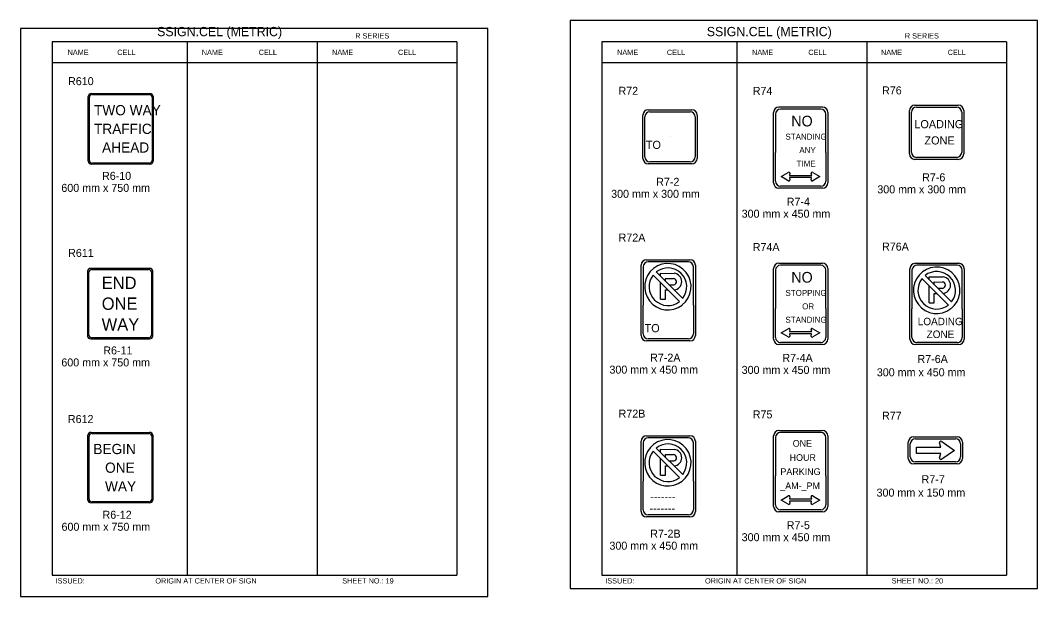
# Model space of a CAD drawing. Extents: x -12 to 6962, y -3756 to 679.
# Drawn here: x -11.9 to 369.4, y -468.8 to -252.7 of the extents above; entities that cross this region are included whole.
import ezdxf

# ---------------------------------------------------------------- set-up
doc = ezdxf.new("R2010")
doc.units = 0
for name, color, linetype in [('Level 1', 7, 'Continuous'), ('Level 2', 7, 'Continuous'), ('Level 3', 7, 'Continuous'), ('Level 63', 7, 'Continuous')]:
    doc.layers.add(name, color=color, linetype=linetype)

msp = doc.modelspace()

# ---------------------------------------------------------------- linework, layer by layer
at = {"layer": 'Level 1'}
for p, q in [((151.75, -260.71), (0, -260.71)), ((0, -260.71), (0, -460.71)), ((50.58, -260.71), (50.58, -460.71)), ((99.37, -260.71), (99.37, -460.71)), ((151.75, -260.71), (151.75, -460.71)), ((357.75, -260.71), (205.99, -260.71)), ((205.99, -260.71), (205.99, -460.71)), ((256.58, -260.71), (256.58, -460.71)), ((305.36, -260.71), (305.36, -460.71)), ((357.75, -260.71), (357.75, -460.71)), ((151.75, -268.62), (0, -268.62)), ((357.75, -268.62), (205.99, -268.62)), ((14, -305.19), (14, -281.51)), ((15.13, -280.53), (36.35, -280.53)), ((37.48, -281.51), (37.48, -305.19)), ((288.09, -285.91), (273.04, -285.91)), ((323.98, -285.23), (339.03, -285.23)), ((222.19, -303.84), (222.19, -288.79)), ((224.07, -286.91), (239.12, -286.91)), ((241, -288.79), (241, -303.84)), ((271.16, -287.79), (271.16, -302.18)), ((289.97, -302.18), (289.97, -287.79)), ((322.1, -302.16), (322.1, -287.11)), ((340.91, -287.11), (340.91, -302.16)), ((25.74, -293.35), (25.74, -293.35)), ((231.6, -296.32), (231.6, -296.32)), ((331.5, -294.64), (331.5, -294.64)), ((280.57, -300.39), (280.57, -300.39)), ((271.16, -313), (271.16, -302.18)), ((289.97, -302.18), (289.97, -313)), ((339.03, -304.04), (323.98, -304.04)), ((36.35, -306.16), (15.13, -306.16)), ((239.12, -305.72), (224.07, -305.72)), ((273.25, -311.24), (275.89, -309.71)), ((275.92, -312.79), (273.25, -311.24)), ((276.54, -309.98), (276.34, -310.83)), ((276.34, -310.83), (280.51, -310.83)), ((280.51, -311.65), (276.35, -311.65)), ((276.35, -311.65), (276.56, -312.51)), ((280.51, -310.83), (284.69, -310.83)), ((284.68, -311.65), (280.51, -311.65)), ((284.47, -312.51), (284.68, -311.65)), ((284.69, -310.83), (284.48, -309.98)), ((287.78, -311.24), (285.11, -312.79)), ((285.13, -309.71), (287.78, -311.24)), ((288.09, -314.88), (273.04, -314.88)), ((14.93, -346.08), (36.15, -346.08)), ((221.55, -345.05), (221.55, -359.44)), ((238.48, -343.17), (223.43, -343.17)), ((240.36, -359.44), (240.36, -345.05)), ((271.16, -346.36), (271.16, -360.75)), ((288.09, -344.48), (273.04, -344.48)), ((289.97, -360.75), (289.97, -346.36)), ((322.28, -346.38), (322.28, -360.78)), ((339.21, -344.51), (324.16, -344.51)), ((341.09, -360.78), (341.09, -346.38)), ((13.8, -370.74), (13.8, -347.06)), ((37.28, -347.06), (37.28, -370.74)), ((225.27, -348.18), (235.18, -358.09)), ((226.44, -347.02), (236.34, -356.92)), ((326, -349.52), (335.91, -359.43)), ((327.18, -348.36), (337.08, -358.26)), ((229.91, -353.72), (230.79, -353.72)), ((231.24, -351.81), (233.02, -351.81)), ((331.97, -353.15), (333.75, -353.15)), ((230.95, -357.65), (230.95, -357.65)), ((330.65, -355.06), (331.53, -355.06)), ((25.54, -358.9), (25.54, -358.9)), ((221.55, -370.26), (221.55, -359.44)), ((240.36, -359.44), (240.36, -370.26)), ((271.16, -371.57), (271.16, -360.75)), ((280.57, -358.96), (280.57, -358.96)), ((289.97, -360.75), (289.97, -371.57)), ((322.28, -371.6), (322.28, -360.78)), ((331.69, -358.99), (331.69, -358.99)), ((341.09, -360.78), (341.09, -371.6)), ((273.25, -369.81), (275.89, -368.28)), ((275.92, -371.36), (273.25, -369.81)), ((276.54, -368.54), (276.34, -369.4)), ((276.34, -369.4), (280.51, -369.4)), ((280.51, -369.4), (284.69, -369.4)), ((284.69, -369.4), (284.48, -368.54)), ((287.78, -369.81), (285.11, -371.36)), ((285.13, -368.28), (287.78, -369.81)), ((36.15, -371.71), (14.93, -371.71)), ((238.48, -372.14), (223.43, -372.14)), ((288.09, -373.45), (273.04, -373.45)), ((280.51, -370.22), (276.35, -370.22)), ((276.35, -370.22), (276.56, -371.08)), ((284.68, -370.22), (280.51, -370.22)), ((284.47, -371.08), (284.68, -370.22)), ((339.21, -373.48), (324.16, -373.48)), ((15, -407.59), (36.22, -407.59)), ((288.09, -407.21), (273.04, -407.21)), ((13.87, -432.24), (13.87, -408.56)), ((37.35, -408.56), (37.35, -432.24)), ((221.55, -411.06), (221.55, -425.45)), ((238.48, -409.18), (223.43, -409.18)), ((240.36, -425.45), (240.36, -411.06)), ((271.16, -409.09), (271.16, -423.48)), ((289.97, -423.48), (289.97, -409.09)), ((321.66, -416.35), (321.66, -411.46)), ((323.54, -409.58), (338.59, -409.58)), ((333.11, -412.71), (332.63, -411.14)), ((333.41, -410.55), (338.26, -413.91)), ((340.47, -411.46), (340.47, -416.35)), ((225.27, -414.19), (235.18, -424.1)), ((226.44, -413.03), (236.34, -422.93)), ((323.94, -415.1), (323.94, -412.71)), ((323.94, -412.71), (333.11, -412.71)), ((333.11, -415.1), (323.94, -415.1)), ((331.06, -413.91), (331.06, -413.91)), ((332.63, -416.67), (333.11, -415.1)), ((338.26, -413.91), (333.41, -417.25)), ((231.24, -417.83), (233.02, -417.83)), ((338.59, -418.23), (323.54, -418.23)), ((25.61, -420.4), (25.61, -420.4)), ((229.91, -419.73), (230.79, -419.73)), ((280.57, -421.7), (280.57, -421.7)), ((221.55, -436.27), (221.55, -425.45)), ((230.95, -423.66), (230.95, -423.66)), ((240.36, -425.45), (240.36, -436.27)), ((271.16, -434.3), (271.16, -423.48)), ((289.97, -423.48), (289.97, -434.3)), ((36.22, -433.22), (15, -433.22)), ((273.25, -432.55), (275.89, -431.01)), ((275.92, -434.09), (273.25, -432.55)), ((276.54, -431.28), (276.34, -432.13)), ((276.34, -432.13), (280.51, -432.13)), ((280.51, -432.95), (276.35, -432.95)), ((276.35, -432.95), (276.56, -433.82)), ((280.51, -432.13), (284.69, -432.13)), ((284.68, -432.95), (280.51, -432.95)), ((284.47, -433.82), (284.68, -432.95)), ((284.69, -432.13), (284.48, -431.28)), ((287.78, -432.55), (285.11, -434.09)), ((285.13, -431.01), (287.78, -432.55)), ((238.48, -438.15), (223.43, -438.15)), ((288.09, -436.18), (273.04, -436.18)), ((0, -460.71), (151.75, -460.71)), ((205.99, -460.71), (357.75, -460.71))]:
    msp.add_line(p, q, dxfattribs=at)
for points in [[(228.01, -348.59), (228.01, -347.51), (233.18, -347.53)], [(229.91, -350.49), (229.91, -349.43), (232.96, -349.44)], [(328.74, -349.93), (328.74, -348.85), (333.92, -348.87)], [(228, -357.23), (228.01, -350.94)], [(228, -357.23), (228, -357.24), (229.91, -357.23), (229.91, -353.72)], [(328.73, -358.57), (328.74, -352.28)], [(330.65, -351.83), (330.65, -350.76), (333.7, -350.78)], [(328.73, -358.57), (328.73, -358.58), (330.65, -358.57), (330.65, -355.06)], [(228.01, -414.6), (228.01, -413.52), (233.18, -413.55)], [(229.91, -416.5), (229.91, -415.44), (232.96, -415.45)], [(228, -423.24), (228.01, -416.95)], [(228, -423.24), (228, -423.25), (229.91, -423.24), (229.91, -419.73)]]:
    msp.add_lwpolyline(points, dxfattribs=at)
for centre, radius, start, end in [((273.04, -287.79), 1.88, 90, 180), ((288.09, -287.79), 1.88, 0, 90), ((323.98, -287.11), 1.88, 90, 180), ((339.03, -287.11), 1.88, 0, 90), ((224.07, -288.79), 1.88, 90, 180), ((239.12, -288.79), 1.88, 0, 90), ((224.07, -303.84), 1.88, 180, 270), ((239.12, -303.84), 1.88, 270, 0), ((323.98, -302.16), 1.88, 180, 270), ((339.03, -302.16), 1.88, 270, 0), ((273.04, -313), 1.88, 180, 270), ((288.09, -313), 1.88, 270, 0), ((223.43, -345.05), 1.88, 90, 180), ((230.8, -352.55), 8.71, 308.1142, 307.7621), ((230.81, -352.55), 7.05, 321.9583, 128.3432), ((238.48, -345.05), 1.88, 0, 90), ((273.04, -346.36), 1.88, 90, 180), ((288.09, -346.36), 1.88, 0, 90), ((324.16, -346.38), 1.88, 90, 180), ((331.54, -353.89), 8.71, 308.1142, 307.7621), ((331.55, -353.89), 7.05, 321.9583, 128.3432), ((339.21, -346.38), 1.88, 0, 90), ((230.81, -352.55), 7.05, 142.1255, 308.3331), ((232.85, -350.63), 1.2, 278.0439, 85.8611), ((232.87, -350.62), 3.11, 274.9803, 84.2691), ((331.55, -353.89), 7.05, 142.1255, 308.3331), ((333.61, -351.96), 3.11, 274.9803, 84.2691), ((333.59, -351.97), 1.2, 278.0439, 85.8611), ((223.43, -370.26), 1.88, 180, 270), ((238.48, -370.26), 1.88, 270, 0), ((273.04, -371.57), 1.88, 180, 270), ((288.09, -371.57), 1.88, 270, 0), ((324.16, -371.6), 1.88, 180, 270), ((339.21, -371.6), 1.88, 270, 0), ((273.04, -409.09), 1.88, 90, 180), ((288.09, -409.09), 1.88, 0, 90), ((223.43, -411.06), 1.88, 90, 180), ((230.8, -418.57), 8.71, 308.1142, 307.7621), ((230.81, -418.56), 7.05, 321.9583, 128.3432), ((238.48, -411.06), 1.88, 0, 90), ((323.54, -411.46), 1.88, 90, 180), ((333.13, -410.99), 0.528, 58.0324, 196.3736), ((338.59, -411.46), 1.88, 0, 90), ((230.81, -418.56), 7.05, 142.1255, 308.3331), ((232.85, -416.64), 1.2, 278.0439, 85.8611), ((232.87, -416.64), 3.11, 274.9803, 84.2691), ((323.54, -416.35), 1.88, 180, 270), ((333.13, -416.81), 0.523, 162.8549, 302.3344), ((338.59, -416.35), 1.88, 270, 0), ((273.04, -434.3), 1.88, 180, 270), ((288.09, -434.3), 1.88, 270, 0), ((223.43, -436.27), 1.88, 180, 270), ((238.48, -436.27), 1.88, 270, 0)]:
    msp.add_arc(centre, radius, start, end, dxfattribs=at)
for centre, major_axis, ratio, start_param, end_param in [((15.13, -281.51), (-1.13, 0), 0.866667, 4.712389, 6.283185), ((36.35, -281.51), (-1.13, 0), 0.866667, 3.141593, 4.712389), ((15.13, -305.19), (1.13, 0), 0.866667, 3.141593, 4.712389), ((36.35, -305.19), (1.13, 0), 0.866667, 4.712389, 6.283185), ((276.15, -309.94), (-0.395, 0), 0.7337, 2.957903, 5.412979), ((276.17, -312.57), (-0.395, 0), 0.7337, 0.835066, 3.34671), ((284.86, -312.57), (-0.395, 0), 0.7337, 6.078068, 8.589712), ((284.88, -309.94), (-0.395, 0), 0.7337, 4.011799, 6.466875), ((14.93, -347.06), (-1.13, 0), 0.866667, 4.712389, 6.283185), ((36.15, -347.06), (-1.13, 0), 0.866667, 3.141593, 4.712389), ((276.15, -368.51), (-0.395, 0), 0.7337, 2.957903, 5.412979), ((284.88, -368.51), (-0.395, 0), 0.7337, 4.011799, 6.466875), ((14.93, -370.74), (1.13, 0), 0.866667, 3.141593, 4.712389), ((36.15, -370.74), (1.13, 0), 0.866667, 4.712389, 6.283185), ((276.17, -371.13), (-0.395, 0), 0.7337, 0.835066, 3.34671), ((284.86, -371.13), (-0.395, 0), 0.7337, 6.078068, 8.589712), ((15, -408.57), (-1.13, 0), 0.866667, 4.712389, 6.283185), ((36.22, -408.57), (-1.13, 0), 0.866667, 3.141593, 4.712389), ((15, -432.24), (1.13, 0), 0.866667, 3.141593, 4.712389), ((36.22, -432.24), (1.13, 0), 0.866667, 4.712389, 6.283185), ((276.15, -431.24), (-0.395, 0), 0.7337, 2.957903, 5.412979), ((276.17, -433.87), (-0.395, 0), 0.7337, 0.835066, 3.34671), ((284.86, -433.87), (-0.395, 0), 0.7337, 6.078068, 8.589712), ((284.88, -431.24), (-0.395, 0), 0.7337, 4.011799, 6.466875)]:
    msp.add_ellipse(centre, major_axis=major_axis, ratio=ratio, start_param=start_param, end_param=end_param, dxfattribs=at)
at = {"layer": 'Level 3'}
for p, q in [((13.55, -305.5), (13.55, -281.2)), ((14.77, -280.14), (36.71, -280.14)), ((37.93, -281.2), (37.93, -305.5)), ((272.44, -285.15), (288.7, -285.15)), ((323.37, -284.48), (339.63, -284.48)), ((221.44, -304.44), (221.44, -288.19)), ((223.47, -286.16), (239.73, -286.16)), ((241.76, -288.19), (241.76, -304.44)), ((270.41, -302.18), (270.41, -287.19)), ((290.73, -287.19), (290.73, -302.18)), ((321.34, -302.76), (321.34, -286.51)), ((341.66, -286.51), (341.66, -302.76)), ((270.41, -313.6), (270.41, -302.18)), ((290.73, -302.18), (290.73, -313.6)), ((339.63, -304.8), (323.37, -304.8)), ((36.71, -306.55), (14.77, -306.55)), ((239.73, -306.48), (223.47, -306.48)), ((288.7, -315.63), (272.44, -315.63)), ((222.83, -342.41), (239.08, -342.41)), ((13.35, -346.75), (13.35, -371.05)), ((36.52, -345.69), (14.57, -345.69)), ((37.73, -371.05), (37.73, -346.75)), ((220.79, -359.44), (220.79, -344.44)), ((241.11, -344.44), (241.11, -359.44)), ((270.41, -360.75), (270.41, -345.75)), ((272.44, -343.72), (288.7, -343.72)), ((290.73, -345.75), (290.73, -360.75)), ((321.53, -360.78), (321.53, -345.78)), ((323.56, -343.75), (339.82, -343.75)), ((341.85, -345.78), (341.85, -360.78)), ((220.79, -370.86), (220.79, -359.44)), ((241.11, -359.44), (241.11, -370.86)), ((270.41, -372.17), (270.41, -360.75)), ((290.73, -360.75), (290.73, -372.17)), ((321.53, -372.2), (321.53, -360.78)), ((341.85, -360.78), (341.85, -372.2)), ((14.57, -372.11), (36.52, -372.11)), ((239.08, -372.89), (222.82, -372.89)), ((288.7, -374.2), (272.44, -374.2)), ((339.82, -374.23), (323.56, -374.23)), ((14.64, -407.2), (36.58, -407.2)), ((272.44, -406.46), (288.7, -406.46)), ((13.42, -432.55), (13.42, -408.25)), ((37.8, -408.25), (37.8, -432.55)), ((220.79, -425.45), (220.79, -410.46)), ((222.83, -408.42), (239.08, -408.42)), ((241.11, -410.46), (241.11, -425.45)), ((270.41, -423.48), (270.41, -408.49)), ((290.73, -408.49), (290.73, -423.48)), ((320.9, -416.95), (320.9, -410.86)), ((322.93, -408.83), (339.19, -408.83)), ((341.22, -410.86), (341.22, -416.95)), ((339.19, -418.98), (322.93, -418.98)), ((220.79, -436.87), (220.79, -425.45)), ((241.11, -425.45), (241.11, -436.87)), ((270.41, -434.91), (270.41, -423.48)), ((290.73, -423.48), (290.73, -434.91)), ((36.58, -433.61), (14.64, -433.61)), ((288.7, -436.94), (272.44, -436.94)), ((239.08, -438.9), (222.82, -438.9))]:
    msp.add_line(p, q, dxfattribs=at)
for centre, start, end in [((272.44, -287.19), 90, 180), ((288.7, -287.19), 0, 90), ((323.37, -286.51), 90, 180), ((339.63, -286.51), 0, 90), ((223.47, -288.19), 90, 180), ((239.73, -288.19), 0, 90), ((223.47, -304.44), 180, 270), ((239.73, -304.44), 270, 0), ((323.37, -302.76), 180, 270), ((339.63, -302.76), 270, 0), ((272.44, -313.6), 180, 270), ((288.7, -313.6), 270, 0), ((222.83, -344.44), 90, 180), ((239.08, -344.44), 0, 90), ((272.44, -345.75), 90, 180), ((288.7, -345.75), 0, 90), ((323.56, -345.78), 90, 180), ((339.82, -345.78), 0, 90), ((222.82, -370.86), 180, 270), ((239.08, -370.86), 270, 0), ((272.44, -372.17), 180, 270), ((288.7, -372.17), 270, 0), ((323.56, -372.2), 180, 270), ((339.82, -372.2), 270, 0), ((272.44, -408.49), 90, 180), ((288.7, -408.49), 0, 90), ((222.83, -410.46), 90, 180), ((239.08, -410.46), 0, 90), ((322.93, -410.86), 90, 180), ((339.19, -410.86), 0, 90), ((322.93, -416.95), 180, 270), ((339.19, -416.95), 270, 0), ((222.82, -436.87), 180, 270), ((239.08, -436.87), 270, 0), ((272.44, -434.91), 180, 270), ((288.7, -434.91), 270, 0)]:
    msp.add_arc(centre, 2.03, start, end, dxfattribs=at)
for centre, major_axis, start_param, end_param in [((14.77, -281.2), (-1.22, 0), 4.712389, 6.283185), ((36.71, -281.2), (-1.22, 0), 3.141593, 4.712389), ((14.77, -305.5), (1.22, 0), 3.141593, 4.712389), ((36.71, -305.5), (1.22, 0), 4.712389, 6.283185), ((14.57, -346.75), (-1.22, 0), 4.712389, 6.283185), ((36.52, -346.75), (-1.22, 0), 3.141593, 4.712389), ((14.57, -371.05), (1.22, 0), 3.141593, 4.712389), ((36.52, -371.05), (1.22, 0), 4.712389, 6.283185), ((14.64, -408.25), (-1.22, 0), 4.712389, 6.283185), ((36.58, -408.25), (-1.22, 0), 3.141593, 4.712389), ((14.64, -432.55), (1.22, 0), 3.141593, 4.712389), ((36.58, -432.55), (1.22, 0), 4.712389, 6.283185)]:
    msp.add_ellipse(centre, major_axis=major_axis, ratio=0.866667, start_param=start_param, end_param=end_param, dxfattribs=at)
at = {"layer": 'Level 63'}
for points in [[(194.12, -465.75), (369.38, -465.75), (369.38, -252.66), (194.12, -252.66)], [(-11.88, -468.77), (163.38, -468.77), (163.38, -255.68), (-11.88, -255.68)]]:
    msp.add_lwpolyline(points, close=True, dxfattribs=at)

# ---------------------------------------------------------------- texts
at = {"layer": 'Level 1'}
for s, height, p in [('TWO WAY', 3.83, (15.72, -288.26)), ('NO', 4, (277.05, -292.44)), ('TRAFFIC', 3.83, (15.73, -295.26)), ('LOADING', 3.048, (323.16, -293.11)), ('STANDING', 2.236, (274.86, -297.41)), ('ZONE', 3.048, (326.95, -299.21)), ('AHEAD', 3.83, (18.76, -302.26)), ('TO       ', 3.048, (222.53, -300.89)), ('ANY', 2.236, (280.07, -302.45)), ('TIME', 2.236, (279.04, -307.49)), ('END', 4.623, (18.61, -353.42)), ('NO', 4, (277.05, -351.01)), ('STOPPING', 2.236, (274.86, -355.98)), ('ONE', 4.623, (18.63, -361.21)), ('OR', 2.236, (281.12, -361.02)), ('WAY', 4.623, (18.59, -369)), ('STANDING', 2.236, (274.86, -366.05)), ('LOADING', 2.8, (324.44, -366.98)), ('TO       ', 3.048, (222.07, -369.6)), ('ZONE', 2.8, (327.75, -371.78)), ('BEGIN', 3.83, (15.48, -415.32)), ('ONE', 2.5, (277.58, -412.55)), ('HOUR', 2.5, (276.42, -417.85)), ('ONE', 3.83, (19.88, -422.32)), ('PARKING', 2.5, (272.97, -423.15)), ('WAY', 3.83, (19.85, -429.32)), ('_AM-_PM', 2.5, (272.92, -428.45)), ('-------', 3.048, (224.13, -432.71)), ('-------', 3.048, (223.96, -437.13))]:
    msp.add_text(s, height=height, dxfattribs=at).set_placement(p)
at = {"layer": 'Level 2'}
for s, p in [('R610', (6.01, -276.97)), ('R72', (212.29, -280.59)), ('R74', (262.61, -280.6)), ('R76', (311.06, -280.44)), ('R6-10', (18.73, -312.48)), ('R7-2', (226.42, -314.71)), ('R7-6', (326.09, -313.03)), ('600 mm x 750 mm', (3.49, -316.98)), ('300 mm x 300 mm', (209.54, -319.21)), ('300 mm x 300 mm', (309.29, -317.53)), ('R7-4', (275.33, -322.17)), ('300 mm x 450 mm', (258.45, -326.67)), ('R72A', (212.33, -335.62)), ('R611', (6.03, -341.38)), ('R74A', (262.61, -339.17)), ('R76A', (311.06, -339.01)), ('R6-11', (19.21, -377.94)), ('600 mm x 750 mm', (3.49, -382.44)), ('R7-2A', (224.14, -380.64)), ('R7-4A', (273.7, -380.74)), ('R7-6A', (324.34, -381.14)), ('300 mm x 450 mm', (208.9, -385.14)), ('300 mm x 450 mm', (258.45, -385.24)), ('300 mm x 450 mm', (309.1, -386.14)), ('R72B', (212.33, -401.64)), ('R75', (262.61, -401.91)), ('R77', (311.06, -402.4)), ('R612', (5.94, -403.67)), ('R7-7', (325.88, -426.25)), ('300 mm x 150 mm', (309.01, -431.25)), ('R6-12', (18.93, -439.56)), ('600 mm x 750 mm', (3.55, -444.06)), ('R7-5', (275.33, -443.48)), ('R7-2B', (224.19, -446.66)), ('300 mm x 450 mm', (258.45, -447.98)), ('300 mm x 450 mm', (208.9, -451.16))]:
    msp.add_text(s, height=3, dxfattribs=at).set_placement(p)
at = {"layer": 'Level 3'}
for s, height, p in [('SSIGN.CEL (METRIC)', 3.4642, (39.38, -258.6)), ('SSIGN.CEL (METRIC)', 3.4642, (245.38, -258.6)), ('R SERIES', 1.979, (113.63, -259.47)), ('R SERIES', 1.979, (319.62, -259.47)), ('NAME', 1.98, (5.81, -265.66)), ('CELL', 1.98, (24.43, -265.66)), ('NAME', 1.98, (56.13, -265.66)), ('CELL', 1.98, (77.45, -265.66)), ('NAME', 1.98, (104.94, -265.66)), ('CELL', 1.98, (129.66, -265.66)), ('NAME', 1.98, (211.76, -265.66)), ('CELL', 1.98, (230.43, -265.66)), ('NAME', 1.98, (262.34, -265.66)), ('CELL', 1.98, (283.44, -265.66)), ('NAME', 1.98, (310.67, -265.66)), ('CELL', 1.98, (335.65, -265.66)), ('ISSUED:', 1.98, (1.34, -463.83)), ('ORIGIN AT CENTER OF SIGN', 1.9795, (38.72, -463.83)), ('SHEET NO.: 19', 1.9795, (108.76, -463.83)), ('ISSUED:', 1.98, (207.33, -463.83)), ('ORIGIN AT CENTER OF SIGN', 1.9795, (244.72, -463.83)), ('SHEET NO.: 20', 1.9795, (314.67, -463.83))]:
    msp.add_text(s, height=height, dxfattribs=at).set_placement(p)

doc.saveas('drawing.dxf')
